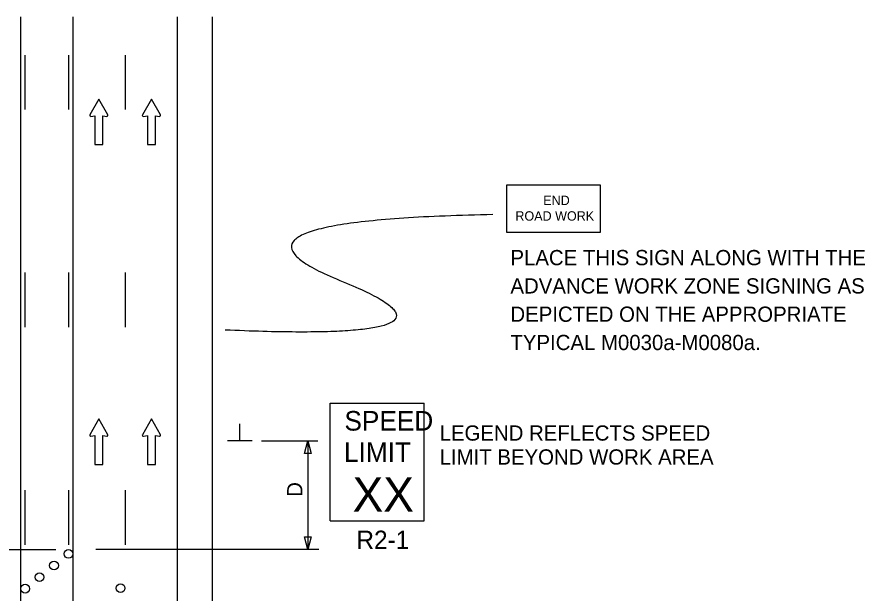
# Model space of a CAD drawing. Extents: x 16733 to 18475, y 5693 to 6915.
# Drawn here: x 17009.8 to 17399.4, y 6628.4 to 6893.1 of the extents above; entities that cross this region are included whole.
import ezdxf

# ---------------------------------------------------------------- set-up
doc = ezdxf.new("R2010")
doc.units = 0
for name, color, linetype in [('ALI_LEGAL_EX', 7, 'Continuous'), ('MT_SCRATCH_LEVEL_E', 7, 'Continuous'), ('PAVT_EDGE_EX', 7, 'Continuous'), ('TRAFFIC_SIGNS_PR', 7, 'Continuous'), ('TYPICAL_TEXT_DIMEN_PR', 7, 'Continuous')]:
    doc.layers.add(name, color=color, linetype=linetype)

msp = doc.modelspace()

# ---------------------------------------------------------------- linework, layer by layer
at = {"layer": 'ALI_LEGAL_EX'}
for points in [[(17013.43, 6875.6), (17013.43, 6850.6)], [(17033.43, 6875.6), (17033.43, 6850.6)], [(17059.43, 6875.6), (17059.43, 6850.6)], [(17013.43, 6775.6), (17013.43, 6750.6)], [(17033.43, 6775.6), (17033.43, 6750.6)], [(17059.43, 6775.6), (17059.43, 6750.6)], [(17013.43, 6675.6), (17013.43, 6650.6)], [(17033.43, 6675.6), (17033.43, 6650.6)], [(17059.43, 6675.6), (17059.43, 6650.6)]]:
    msp.add_lwpolyline(points, dxfattribs=at)
at = {"layer": 'MT_SCRATCH_LEVEL_E'}
for p, q in [((17047.37, 6855.34), (17043.26, 6848.1)), ((17047.37, 6855.34), (17043.26, 6848.1)), ((17051.52, 6848.1), (17047.37, 6855.34)), ((17051.52, 6848.1), (17047.37, 6855.34)), ((17071.54, 6855.34), (17067.43, 6848.1)), ((17071.54, 6855.34), (17067.43, 6848.1)), ((17075.69, 6848.1), (17071.54, 6855.34)), ((17075.69, 6848.1), (17071.54, 6855.34)), ((17043.74, 6847.41), (17045.52, 6847.73)), ((17043.74, 6847.41), (17045.52, 6847.73)), ((17045.52, 6847.73), (17045.52, 6834.47)), ((17045.52, 6847.73), (17045.52, 6834.47)), ((17049.26, 6834.47), (17049.26, 6847.73)), ((17049.26, 6847.73), (17051.04, 6847.41)), ((17049.26, 6834.47), (17049.26, 6847.73)), ((17049.26, 6847.73), (17051.04, 6847.41)), ((17067.91, 6847.41), (17069.69, 6847.73)), ((17067.91, 6847.41), (17069.69, 6847.73)), ((17069.69, 6847.73), (17069.69, 6834.47)), ((17069.69, 6847.73), (17069.69, 6834.47)), ((17073.43, 6834.47), (17073.43, 6847.73)), ((17073.43, 6847.73), (17075.21, 6847.41)), ((17073.43, 6834.47), (17073.43, 6847.73)), ((17073.43, 6847.73), (17075.21, 6847.41)), ((17045.52, 6834.47), (17049.26, 6834.47)), ((17045.52, 6834.47), (17049.26, 6834.47)), ((17069.69, 6834.47), (17073.43, 6834.47)), ((17069.69, 6834.47), (17073.43, 6834.47)), ((17047.37, 6708.37), (17043.26, 6701.13)), ((17047.37, 6708.37), (17043.26, 6701.13)), ((17051.52, 6701.13), (17047.37, 6708.37)), ((17051.52, 6701.13), (17047.37, 6708.37)), ((17071.54, 6708.37), (17067.43, 6701.13)), ((17071.54, 6708.37), (17067.43, 6701.13)), ((17075.69, 6701.13), (17071.54, 6708.37)), ((17075.69, 6701.13), (17071.54, 6708.37)), ((17043.74, 6700.45), (17045.52, 6700.76)), ((17043.74, 6700.45), (17045.52, 6700.76)), ((17045.52, 6700.76), (17045.52, 6687.51)), ((17045.52, 6700.76), (17045.52, 6687.51)), ((17049.26, 6687.51), (17049.26, 6700.76)), ((17049.26, 6700.76), (17051.04, 6700.45)), ((17049.26, 6687.51), (17049.26, 6700.76)), ((17049.26, 6700.76), (17051.04, 6700.45)), ((17067.91, 6700.45), (17069.69, 6700.76)), ((17067.91, 6700.45), (17069.69, 6700.76)), ((17069.69, 6700.76), (17069.69, 6687.51)), ((17069.69, 6700.76), (17069.69, 6687.51)), ((17073.43, 6687.51), (17073.43, 6700.76)), ((17073.43, 6700.76), (17075.21, 6700.45)), ((17073.43, 6687.51), (17073.43, 6700.76)), ((17073.43, 6700.76), (17075.21, 6700.45)), ((17045.52, 6687.51), (17049.26, 6687.51)), ((17045.52, 6687.51), (17049.26, 6687.51)), ((17069.69, 6687.51), (17073.43, 6687.51)), ((17069.69, 6687.51), (17073.43, 6687.51))]:
    msp.add_line(p, q, dxfattribs=at)
for centre, start, end in [((17043.67, 6847.87), 150.4248, 279.9638), ((17043.67, 6847.87), 150.4248, 279.9638), ((17051.11, 6847.87), 260.0362, 29.7731), ((17051.11, 6847.87), 260.0362, 29.7731), ((17067.84, 6847.87), 150.4248, 279.9638), ((17067.84, 6847.87), 150.4248, 279.9638), ((17075.28, 6847.87), 260.0362, 29.7731), ((17075.28, 6847.87), 260.0362, 29.7731), ((17043.67, 6700.91), 150.4248, 279.9638), ((17043.67, 6700.91), 150.4248, 279.9638), ((17051.11, 6700.91), 260.0362, 29.7731), ((17051.11, 6700.91), 260.0362, 29.7731), ((17067.84, 6700.91), 150.4248, 279.9638), ((17067.84, 6700.91), 150.4248, 279.9638), ((17075.28, 6700.91), 260.0362, 29.7731), ((17075.28, 6700.91), 260.0362, 29.7731)]:
    msp.add_arc(centre, 0.463, start, end, dxfattribs=at)
at = {"layer": 'PAVT_EDGE_EX'}
for p, q in [((17011.43, 6893.09), (17011.43, 6095.81)), ((17035.43, 6893.09), (17035.43, 6095.81)), ((17083.43, 6893.09), (17083.43, 6095.81)), ((17099.43, 6893.09), (17099.43, 6095.81))]:
    msp.add_line(p, q, dxfattribs=at)
at = {"layer": 'TRAFFIC_SIGNS_PR'}
for p, q in [((17153.72, 6715.56), (17196.92, 6715.56)), ((17153.72, 6661.56), (17153.72, 6715.56)), ((17196.92, 6661.56), (17196.92, 6715.56)), ((17153.72, 6661.56), (17196.92, 6661.56))]:
    msp.add_line(p, q, dxfattribs=at)
msp.add_lwpolyline([(17234.69, 6794.16), (17277.89, 6794.16), (17277.89, 6815.76), (17234.69, 6815.76)], close=True, dxfattribs=at)
for centre in [(17033.43, 6646.35), (17026.8, 6641.03), (17020.17, 6635.72), (17013.53, 6630.4), (17013.53, 6630.4), (17057.41, 6630.63)]:
    msp.add_circle(centre, 2, dxfattribs=at)
msp.add_open_spline([(17228.4, 6802.25), (17089.56, 6799.6), (17228.53, 6743.73), (17105.43, 6749.22)], degree=2, dxfattribs=at)
at = {"layer": 'TYPICAL_TEXT_DIMEN_PR'}
for p, q in [((17112.19, 6698.38), (17112.19, 6706.16)), ((17117.82, 6698.38), (17106.57, 6698.38)), ((17122.07, 6698.38), (17148.07, 6698.38)), ((17141.86, 6692.52), (17143.43, 6698.38)), ((17143.43, 6698.38), (17143.43, 6648.38)), ((17143.43, 6698.38), (17145, 6692.52)), ((17143.43, 6692.52), (17141.86, 6692.52)), ((17145, 6692.52), (17143.43, 6692.52)), ((17143.43, 6648.38), (17141.86, 6654.24)), ((17141.86, 6654.24), (17143.43, 6654.24)), ((17143.43, 6654.24), (17145, 6654.24)), ((17145, 6654.24), (17143.43, 6648.38)), ((16898.43, 6648.38), (17027.57, 6648.38)), ((17148.43, 6648.38), (17046.02, 6648.38))]:
    msp.add_line(p, q, dxfattribs=at)

# ---------------------------------------------------------------- texts
at = {"layer": 'TRAFFIC_SIGNS_PR'}
for s, height, p in [('END', 4.31, (17251.56, 6806.68)), ('ROAD WORK', 4.31, (17238.75, 6799.5)), ('PLACE THIS SIGN ALONG WITH THE', 7, (17236.47, 6779.02)), ('ADVANCE WORK ZONE SIGNING AS', 7, (17236.47, 6766.02)), ('DEPICTED ON THE APPROPRIATE', 7, (17236.47, 6753.02)), ('TYPICAL M0030a-M0080a.', 7, (17236.47, 6740.02)), ('SPEED', 9, (17160.21, 6703.03)), ('LIMIT', 9, (17160.02, 6688.63)), ('XX', 15.785, (17163.97, 6665.79)), ('R2-1', 8.37, (17165.73, 6648.69))]:
    msp.add_text(s, height=height, dxfattribs=at).set_placement(p)
at = {"layer": 'TYPICAL_TEXT_DIMEN_PR'}
for s, p in [('LEGEND REFLECTS SPEED', (17203.94, 6698.42)), ('LIMIT BEYOND WORK AREA', (17203.94, 6687.42))]:
    msp.add_text(s, height=7, dxfattribs=at).set_placement(p)
msp.add_text('D', height=7, rotation=90, dxfattribs=at).set_placement((17140.88, 6672.6))

doc.saveas('drawing.dxf')
